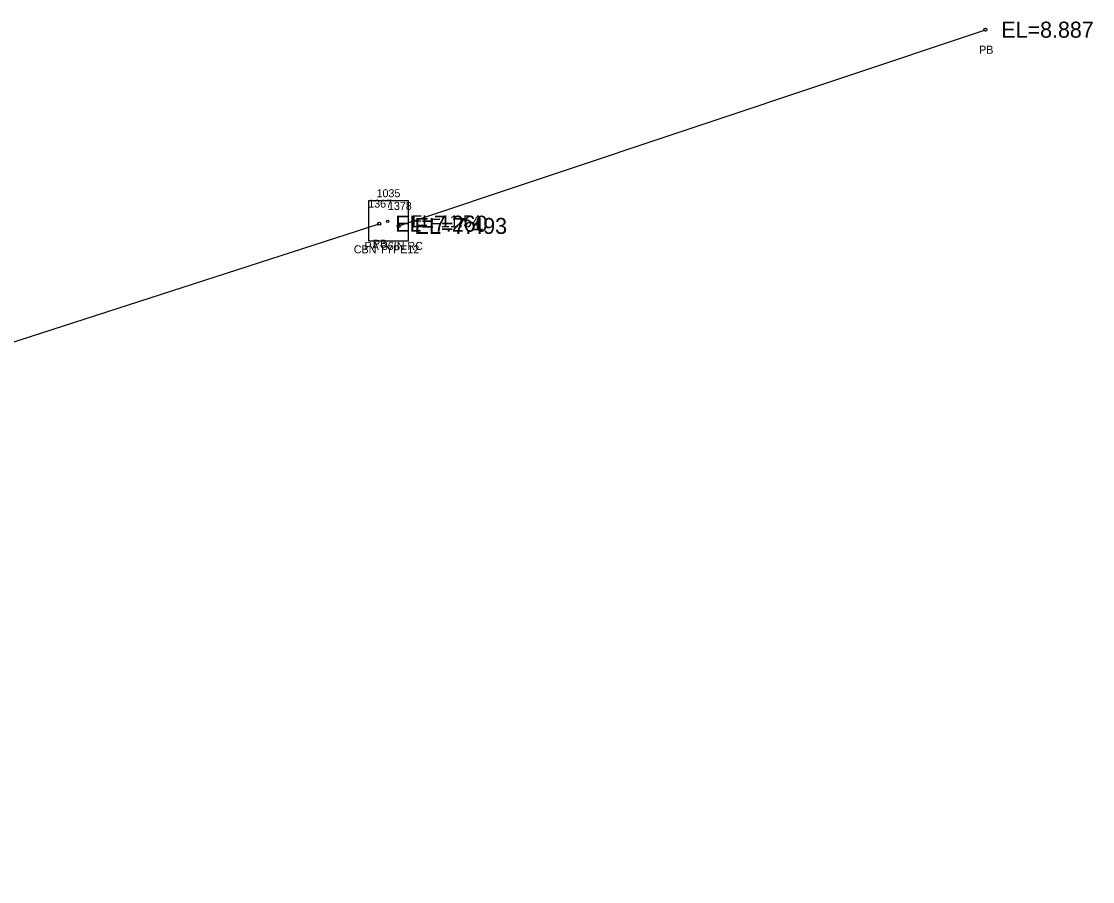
# Model space of a CAD drawing. Extents: x 2072307 to 2072993, y 127574 to 129736.
# Drawn here: x 2072623.4 to 2072757.2, y 129153.5 to 129260.9 of the extents above; entities that cross this region are included whole.
import ezdxf

# ---------------------------------------------------------------- set-up
doc = ezdxf.new("R2010")
doc.units = 0
for name, color, linetype in [('RD_EX_DR_Inlet', 7, 'Continuous'), ('RD_EX_DR_Inlet_txCode', 7, 'Continuous'), ('RD_EX_DR_Pipe', 7, 'Continuous'), ('RD_EX_DR_Pipe_txCode', 7, 'Continuous'), ('RD_EX_TX_DR_Inlet_ELEV', 7, 'Continuous'), ('RD_SMD_Locator', 7, 'Continuous'), ('RD_TX_Pipe_ElevEX', 7, 'Continuous')]:
    doc.layers.add(name, color=color, linetype=linetype)

msp = doc.modelspace()

# ---------------------------------------------------------------- linework, layer by layer
at = {"layer": 'RD_EX_DR_Inlet'}
msp.add_line((2072671.74, 129233.5), (2072671.74, 129238.5), dxfattribs=at)
msp.add_lwpolyline([(2072671.74, 129233.5), (2072671.74, 129238.5), (2072666.74, 129238.5), (2072666.74, 129233.5)], close=True, dxfattribs=at)
at = {"layer": 'RD_EX_DR_Pipe'}
for p, q in [((2072670.53, 129235.37), (2072743.8, 129259.87)), ((2072413.78, 129153.52), (2072668.09, 129235.65))]:
    msp.add_line(p, q, dxfattribs=at)
at = {"layer": 'RD_SMD_Locator'}
for centre, radius in [((2072743.8, 129259.87), 0.2), ((2072668.09, 129235.65), 0.2), ((2072669.15, 129235.95), 0.15), ((2072670.53, 129235.37), 0.2)]:
    msp.add_circle(centre, radius, dxfattribs=at)

# ---------------------------------------------------------------- texts
at = {"layer": 'RD_EX_DR_Inlet_txCode'}
for s, p in [('1035', (2072667.76, 129238.95)), ('CBN TYPE12', (2072664.92, 129231.95))]:
    msp.add_text(s, height=1, dxfattribs=at).set_placement(p)
at = {"layer": 'RD_EX_DR_Pipe_txCode'}
for s, p in [('PB', (2072743.02, 129256.87)), ('1367', (2072666.72, 129237.65)), ('1378', (2072669.18, 129237.37)), ('PA 36IN RC', (2072666.27, 129232.37)), ('PB', (2072667.31, 129232.65))]:
    msp.add_text(s, height=1, dxfattribs=at).set_placement(p)
at = {"layer": 'RD_EX_TX_DR_Inlet_ELEV'}
msp.add_text('EL=11.54', height=1.5, dxfattribs=at).set_placement((2072672.15, 129235.2))
at = {"layer": 'RD_TX_Pipe_ElevEX'}
for s, p in [('EL=8.887', (2072745.8, 129258.87)), ('EL=7.260', (2072670.09, 129234.65)), ('EL=7.493', (2072672.53, 129234.37))]:
    msp.add_text(s, height=2, dxfattribs=at).set_placement(p)

doc.saveas('drawing.dxf')
